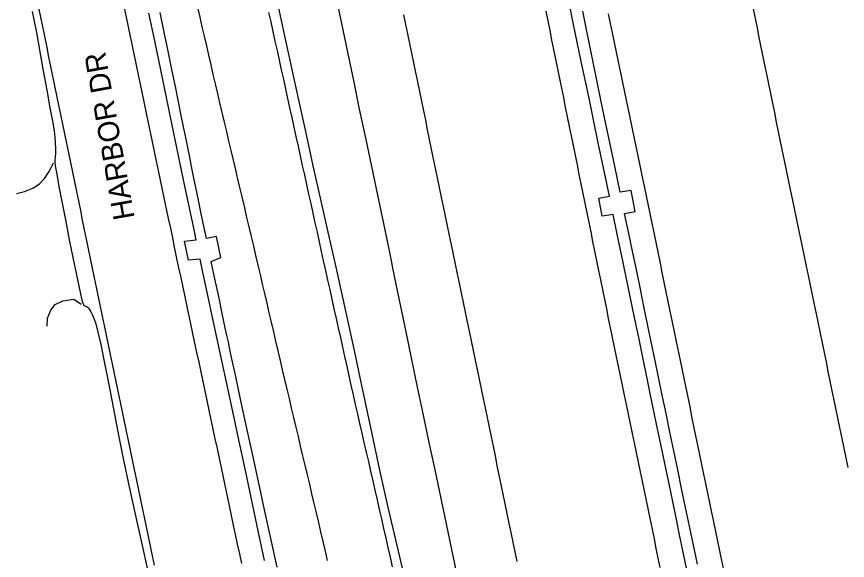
# Model space of a CAD drawing. Extents: x 1948091 to 1975253, y 787267 to 823306.
# Drawn here: x 1966655.1 to 1966867.3, y 788495.7 to 788634.5 of the extents above; entities that cross this region are included whole.
import ezdxf

# ---------------------------------------------------------------- set-up
doc = ezdxf.new("R2010")
doc.units = 0
for name, color, linetype in [('RD_EX_Pavement_Markings', 7, 'Continuous'), ('RD_EX_Road', 7, 'Continuous'), ('RD_TX_RoadID', 7, 'Continuous')]:
    doc.layers.add(name, color=color, linetype=linetype)

msp = doc.modelspace()

# ---------------------------------------------------------------- linework, layer by layer
at = {"layer": 'RD_EX_Pavement_Markings'}
for points in [[(1966690.28, 788494.44), (1966689.77, 788496.88), (1966689.26, 788499.33), (1966688.75, 788501.78), (1966688.24, 788504.22), (1966687.72, 788506.67), (1966687.21, 788509.12), (1966686.7, 788511.56), (1966686.19, 788514.01), (1966685.68, 788516.46), (1966685.17, 788518.91), (1966684.65, 788521.35), (1966684.14, 788523.8), (1966683.63, 788526.25), (1966683.12, 788528.69), (1966682.61, 788531.14), (1966682.1, 788533.59), (1966681.58, 788536.03), (1966681.07, 788538.48), (1966680.56, 788540.93), (1966680.05, 788543.38), (1966679.54, 788545.82), (1966679.03, 788548.27), (1966678.51, 788550.72), (1966678, 788553.16), (1966677.49, 788555.61), (1966676.99, 788558.06), (1966676.48, 788560.51), (1966675.98, 788562.96), (1966675.48, 788565.41), (1966674.97, 788567.85), (1966674.47, 788570.3), (1966673.97, 788572.75), (1966673.46, 788575.2), (1966672.96, 788577.65), (1966672.46, 788580.1), (1966671.95, 788582.55), (1966671.45, 788585), (1966670.95, 788587.44), (1966670.44, 788589.89), (1966669.94, 788592.34), (1966669.44, 788594.79), (1966668.93, 788597.24), (1966668.43, 788599.69), (1966667.93, 788602.14), (1966667.42, 788604.59), (1966666.91, 788607.03), (1966666.4, 788609.48), (1966665.89, 788611.93), (1966665.39, 788614.38), (1966664.88, 788616.82), (1966664.37, 788619.27), (1966663.86, 788621.72), (1966663.35, 788624.17), (1966662.84, 788626.61), (1966662.33, 788629.06), (1966661.82, 788631.51), (1966661.31, 788633.96), (1966660.8, 788636.4)], [(1966712.58, 788494.91), (1966712.06, 788497.35), (1966711.54, 788499.8), (1966711.02, 788502.25), (1966710.5, 788504.69), (1966709.98, 788507.14), (1966709.46, 788509.58), (1966708.94, 788512.03), (1966708.43, 788514.47), (1966707.91, 788516.92), (1966707.39, 788519.36), (1966706.87, 788521.81), (1966706.35, 788524.26), (1966705.83, 788526.7), (1966705.31, 788529.15), (1966704.79, 788531.59), (1966704.27, 788534.04), (1966703.75, 788536.48), (1966703.23, 788538.93), (1966702.71, 788541.37), (1966702.19, 788543.82), (1966701.67, 788546.26), (1966701.15, 788548.71), (1966700.63, 788551.15), (1966700.11, 788553.6), (1966699.59, 788556.04), (1966699.07, 788558.49), (1966698.55, 788560.93), (1966698.03, 788563.38), (1966697.51, 788565.82), (1966696.99, 788568.27), (1966696.47, 788570.72), (1966695.96, 788573.16), (1966695.45, 788575.61), (1966694.94, 788578.06), (1966694.43, 788580.5), (1966693.91, 788582.95), (1966693.4, 788585.4), (1966692.89, 788587.84), (1966692.38, 788590.29), (1966691.87, 788592.74), (1966691.36, 788595.19), (1966690.84, 788597.63), (1966690.33, 788600.08), (1966689.82, 788602.53), (1966689.31, 788604.97), (1966688.8, 788607.42), (1966688.29, 788609.87), (1966687.77, 788612.31), (1966687.26, 788614.76), (1966686.75, 788617.21), (1966686.24, 788619.66), (1966685.73, 788622.1), (1966685.22, 788624.55), (1966684.71, 788627), (1966684.19, 788629.44), (1966683.68, 788631.89), (1966683.17, 788634.34), (1966682.66, 788636.78)], [(1966701.3, 788636.8), (1966701.87, 788634.37), (1966702.43, 788631.93), (1966702.99, 788629.49), (1966703.56, 788627.06), (1966704.12, 788624.62), (1966704.68, 788622.19), (1966705.24, 788619.75), (1966705.81, 788617.31), (1966706.37, 788614.88), (1966706.94, 788612.45), (1966707.52, 788610.01), (1966708.09, 788607.58), (1966708.67, 788605.15), (1966709.24, 788602.71), (1966709.82, 788600.28), (1966710.39, 788597.85), (1966710.96, 788595.41), (1966711.54, 788592.98), (1966712.11, 788590.55), (1966712.69, 788588.12), (1966713.26, 788585.68), (1966713.84, 788583.25), (1966714.41, 788580.82), (1966714.99, 788578.38), (1966715.56, 788575.95), (1966716.12, 788573.51), (1966716.69, 788571.08), (1966717.26, 788568.65), (1966717.83, 788566.21), (1966718.4, 788563.78), (1966718.97, 788561.34), (1966719.54, 788558.91), (1966720.11, 788556.47), (1966720.68, 788554.04), (1966721.24, 788551.61), (1966721.81, 788549.17), (1966722.38, 788546.74), (1966722.95, 788544.3), (1966723.52, 788541.87), (1966724.09, 788539.43), (1966724.67, 788537), (1966725.25, 788534.57), (1966725.82, 788532.14), (1966726.4, 788529.7), (1966726.98, 788527.27), (1966727.55, 788524.84), (1966728.13, 788522.41), (1966728.71, 788519.97), (1966729.28, 788517.54), (1966729.86, 788515.11), (1966730.44, 788512.68), (1966731.01, 788510.24), (1966731.59, 788507.81), (1966732.17, 788505.38), (1966732.73, 788502.94), (1966733.3, 788500.51), (1966733.87, 788498.07), (1966734.43, 788495.64)], [(1966867.51, 788519.41), (1966867, 788521.86), (1966866.49, 788524.31), (1966865.99, 788526.76), (1966865.48, 788529.21), (1966864.97, 788531.65), (1966864.46, 788534.1), (1966863.95, 788536.55), (1966863.44, 788539), (1966862.93, 788541.44), (1966862.42, 788543.89), (1966861.91, 788546.34), (1966861.4, 788548.79), (1966860.89, 788551.23), (1966860.39, 788553.68), (1966859.88, 788556.13), (1966859.37, 788558.58), (1966858.86, 788561.02), (1966858.35, 788563.47), (1966857.84, 788565.92), (1966857.33, 788568.37), (1966856.82, 788570.81), (1966856.31, 788573.26), (1966855.8, 788575.71), (1966855.3, 788578.16), (1966854.79, 788580.6), (1966854.28, 788583.05), (1966853.77, 788585.5), (1966853.26, 788587.95), (1966852.75, 788590.39), (1966852.24, 788592.84), (1966851.73, 788595.29), (1966851.23, 788597.74), (1966850.73, 788600.19), (1966850.22, 788602.64), (1966849.72, 788605.09), (1966849.22, 788607.53), (1966848.72, 788609.98), (1966848.22, 788612.43), (1966847.71, 788614.88), (1966847.21, 788617.33), (1966846.71, 788619.78), (1966846.21, 788622.23), (1966845.7, 788624.68), (1966845.2, 788627.13), (1966844.7, 788629.58), (1966844.2, 788632.02), (1966843.7, 788634.47), (1966843.19, 788636.92)], [(1966719.46, 788635.59), (1966719.99, 788633.15), (1966720.53, 788630.7), (1966721.07, 788628.26), (1966721.6, 788625.82), (1966722.14, 788623.38), (1966722.67, 788620.94), (1966723.21, 788618.5), (1966723.75, 788616.05), (1966724.28, 788613.61), (1966724.82, 788611.17), (1966725.36, 788608.73), (1966725.9, 788606.29), (1966726.43, 788603.85), (1966726.97, 788601.4), (1966727.51, 788598.96), (1966728.05, 788596.52), (1966728.58, 788594.08), (1966729.12, 788591.64), (1966729.66, 788589.2), (1966730.2, 788586.76), (1966730.73, 788584.31), (1966731.27, 788581.87), (1966731.81, 788579.43), (1966732.34, 788576.99), (1966732.88, 788574.55), (1966733.42, 788572.11), (1966733.96, 788569.67), (1966734.5, 788567.23), (1966735.05, 788564.79), (1966735.59, 788562.35), (1966736.13, 788559.91), (1966736.68, 788557.47), (1966737.22, 788555.03), (1966737.77, 788552.59), (1966738.31, 788550.14), (1966738.85, 788547.7), (1966739.4, 788545.26), (1966739.94, 788542.82), (1966740.49, 788540.38), (1966741.03, 788537.94), (1966741.58, 788535.51), (1966742.14, 788533.07), (1966742.69, 788530.63), (1966743.25, 788528.19), (1966743.81, 788525.76), (1966744.36, 788523.32), (1966744.92, 788520.88), (1966745.47, 788518.44), (1966746.03, 788516.01), (1966746.58, 788513.57), (1966747.14, 788511.13), (1966747.7, 788508.7), (1966748.25, 788506.26), (1966748.81, 788503.82), (1966749.36, 788501.38), (1966749.92, 788498.95), (1966750.47, 788496.51), (1966751.03, 788494.07)], [(1966753.93, 788634.96), (1966754.44, 788632.51), (1966754.94, 788630.06), (1966755.45, 788627.61), (1966755.95, 788625.16), (1966756.46, 788622.72), (1966756.96, 788620.27), (1966757.46, 788617.82), (1966757.97, 788615.37), (1966758.47, 788612.92), (1966758.98, 788610.47), (1966759.48, 788608.02), (1966759.98, 788605.58), (1966760.49, 788603.13), (1966760.99, 788600.68), (1966761.5, 788598.23), (1966762, 788595.78), (1966762.51, 788593.33), (1966763.01, 788590.88), (1966763.52, 788588.44), (1966764.03, 788585.99), (1966764.54, 788583.54), (1966765.05, 788581.09), (1966765.56, 788578.65), (1966766.07, 788576.2), (1966766.57, 788573.75), (1966767.08, 788571.3), (1966767.59, 788568.86), (1966768.1, 788566.41), (1966768.61, 788563.96), (1966769.12, 788561.52), (1966769.63, 788559.07), (1966770.14, 788556.62), (1966770.65, 788554.17), (1966771.16, 788551.73), (1966771.67, 788549.28), (1966772.18, 788546.83), (1966772.69, 788544.38), (1966773.2, 788541.94), (1966773.71, 788539.49), (1966774.22, 788537.04), (1966774.73, 788534.59), (1966775.24, 788532.15), (1966775.75, 788529.7), (1966776.26, 788527.25), (1966776.77, 788524.8), (1966777.28, 788522.36), (1966777.78, 788519.91), (1966778.29, 788517.46), (1966778.79, 788515.01), (1966779.3, 788512.56), (1966779.8, 788510.11), (1966780.31, 788507.67), (1966780.82, 788505.22), (1966781.32, 788502.77), (1966781.83, 788500.32), (1966782.33, 788497.87), (1966782.84, 788495.42)], [(1966790.24, 788635.86), (1966790.74, 788633.41), (1966791.24, 788630.96), (1966791.74, 788628.51), (1966792.24, 788626.06), (1966792.74, 788623.61), (1966793.24, 788621.16), (1966793.74, 788618.71), (1966794.24, 788616.26), (1966794.74, 788613.82), (1966795.24, 788611.37), (1966795.74, 788608.92), (1966796.23, 788606.47), (1966796.73, 788604.02), (1966797.23, 788601.57), (1966797.73, 788599.12), (1966798.23, 788596.67), (1966798.73, 788594.22), (1966799.23, 788591.77), (1966799.73, 788589.32), (1966800.23, 788586.87), (1966800.73, 788584.42), (1966801.23, 788581.97), (1966801.72, 788579.52), (1966802.22, 788577.07), (1966802.72, 788574.62), (1966803.22, 788572.17), (1966803.72, 788569.72), (1966804.22, 788567.27), (1966804.72, 788564.82), (1966805.22, 788562.37), (1966805.72, 788559.92), (1966806.22, 788557.47), (1966806.71, 788555.02), (1966807.21, 788552.57), (1966807.71, 788550.12), (1966808.21, 788547.68), (1966808.71, 788545.23), (1966809.22, 788542.78), (1966809.73, 788540.33), (1966810.24, 788537.88), (1966810.75, 788535.44), (1966811.26, 788532.99), (1966811.77, 788530.54), (1966812.28, 788528.09), (1966812.79, 788525.65), (1966813.3, 788523.2), (1966813.81, 788520.75), (1966814.32, 788518.3), (1966814.83, 788515.86), (1966815.34, 788513.41), (1966815.85, 788510.96), (1966816.36, 788508.51), (1966816.87, 788506.07), (1966817.38, 788503.62), (1966817.89, 788501.17), (1966818.4, 788498.73), (1966818.91, 788496.28), (1966819.42, 788493.83)], [(1966806.2, 788635.22), (1966806.71, 788632.77), (1966807.22, 788630.33), (1966807.73, 788627.88), (1966808.24, 788625.43), (1966808.75, 788622.98), (1966809.26, 788620.54), (1966809.77, 788618.09), (1966810.28, 788615.64), (1966810.79, 788613.19), (1966811.3, 788610.75), (1966811.81, 788608.3), (1966812.32, 788605.85), (1966812.83, 788603.4), (1966813.34, 788600.96), (1966813.84, 788598.51), (1966814.35, 788596.06), (1966814.86, 788593.62), (1966815.37, 788591.17), (1966815.88, 788588.72), (1966816.39, 788586.27), (1966816.9, 788583.83), (1966817.41, 788581.38), (1966817.91, 788578.93), (1966818.42, 788576.48), (1966818.92, 788574.03), (1966819.43, 788571.58), (1966819.93, 788569.13), (1966820.44, 788566.69), (1966820.94, 788564.24), (1966821.45, 788561.79), (1966821.95, 788559.34), (1966822.46, 788556.89), (1966822.96, 788554.44), (1966823.47, 788552), (1966823.97, 788549.55), (1966824.48, 788547.1), (1966824.98, 788544.65), (1966825.49, 788542.2), (1966825.99, 788539.75), (1966826.5, 788537.31), (1966827, 788534.86), (1966827.51, 788532.41), (1966828.02, 788529.96), (1966828.52, 788527.51), (1966829.03, 788525.06), (1966829.53, 788522.62), (1966830.04, 788520.17), (1966830.54, 788517.72), (1966831.05, 788515.27), (1966831.56, 788512.82), (1966832.07, 788510.38), (1966832.57, 788507.93), (1966833.08, 788505.48), (1966833.59, 788503.03), (1966834.1, 788500.58), (1966834.6, 788498.14), (1966835.11, 788495.69), (1966835.62, 788493.24)]]:
    msp.add_lwpolyline(points, dxfattribs=at)
at = {"layer": 'RD_EX_Road'}
for points in [[(1966754.04, 788491.93), (1966751.93, 788500.9), (1966749.92, 788509.59), (1966747.89, 788518.7), (1966745.88, 788528.01), (1966744.27, 788535.6), (1966743.03, 788541.51), (1966741.63, 788548.03), (1966740.01, 788555.47), (1966738.3, 788563.25), (1966736.53, 788571.26), (1966734.69, 788579.46), (1966732.79, 788587.84), (1966730.87, 788596.44), (1966728.95, 788605.18), (1966727.1, 788613.63), (1966725.31, 788621.75), (1966723.53, 788629.93), (1966721.72, 788638.23)], [(1966736.55, 788640.07), (1966738.07, 788632.72), (1966739.58, 788625.45), (1966741.09, 788618.19), (1966742.62, 788610.91), (1966744.16, 788603.58), (1966745.72, 788596.21), (1966747.26, 788588.9), (1966748.76, 788581.72), (1966750.22, 788574.69), (1966751.64, 788567.8), (1966753.05, 788560.94), (1966754.49, 788554), (1966755.95, 788546.99), (1966757.43, 788539.89), (1966758.92, 788532.79), (1966760.4, 788525.75), (1966761.87, 788518.77), (1966763.32, 788511.86), (1966764.77, 788504.97), (1966766.22, 788498.07), (1966767.68, 788491.16)], [(1966826.29, 788493.23), (1966825.34, 788497.78), (1966824.42, 788502.2), (1966823.53, 788506.5), (1966822.67, 788510.68), (1966821.82, 788514.77), (1966820.98, 788518.83), (1966820.14, 788522.85), (1966819.31, 788526.84), (1966818.48, 788530.85), (1966817.63, 788534.95), (1966816.76, 788539.13), (1966815.88, 788543.4), (1966814.96, 788547.86), (1966813.98, 788552.61), (1966812.93, 788557.66), (1966811.82, 788563.01), (1966810.69, 788568.44), (1966809.59, 788573.75), (1966808.51, 788578.94), (1966807.46, 788584), (1966804.68, 788583.58), (1966803.78, 788588.19), (1966806.5, 788588.66), (1966804.99, 788595.89), (1966803.66, 788602.25), (1966802.52, 788607.74), (1966801.55, 788612.36), (1966800.61, 788616.83), (1966799.56, 788621.88), (1966798.39, 788627.52), (1966797.11, 788633.74), (1966795.79, 788640.12)], [(1966659.07, 788635.79), (1966660.12, 788630.43), (1966661.04, 788625.47), (1966661.9, 788620.65), (1966662.79, 788615.71), (1966663.59, 788611.24), (1966664.21, 788607.83), (1966664.64, 788605.34), (1966664.85, 788603.63), (1966664.95, 788602.26), (1966665.01, 788600.81), (1966665.01, 788599.51), (1966664.92, 788598.58), (1966664.82, 788597.91), (1966664.8, 788597.63), (1966664.8, 788597.39), (1966664.94, 788596.4), (1966665.31, 788594.31), (1966665.9, 788591.13), (1966666.71, 788586.89), (1966667.62, 788582.16), (1966668.54, 788577.53), (1966669.45, 788573), (1966670.35, 788568.59), (1966671.12, 788564.9), (1966671.63, 788562.53), (1966671.83, 788561.77), (1966672.04, 788561.21), (1966672.27, 788560.85), (1966672.51, 788560.69), (1966672.74, 788560.61), (1966672.97, 788560.49), (1966673.18, 788560.32), (1966673.38, 788560.11), (1966673.58, 788559.85), (1966674.01, 788559.16), (1966674.46, 788558.26), (1966674.89, 788557.25), (1966675.31, 788556.04), (1966675.86, 788553.92), (1966676.55, 788550.75), (1966677.46, 788546.42), (1966678.57, 788540.97), (1966679.76, 788534.8), (1966681.01, 788528.06), (1966682.37, 788521.27), (1966683.85, 788514.47), (1966685.38, 788507.47), (1966686.96, 788500.27), (1966688.56, 788492.94)], [(1966718.38, 788495.62), (1966716.75, 788503.25), (1966715.74, 788508.04), (1966714.64, 788513.31), (1966713.43, 788519.08), (1966712.12, 788525.22), (1966710.91, 788530.91), (1966709.79, 788536.09), (1966708.67, 788541.19), (1966707.55, 788546.26), (1966705.54, 788555.7), (1966703.56, 788564.93), (1966702.49, 788569.99), (1966701.95, 788572.6), (1966699.01, 788572.33), (1966697.98, 788577.2), (1966700.94, 788577.49), (1966700.23, 788580.92), (1966699.09, 788586.42), (1966697.74, 788592.86), (1966696.19, 788600.2), (1966694.74, 788607.23), (1966693.38, 788613.88), (1966691.92, 788620.91), (1966690.35, 788628.33), (1966688.85, 788635.37)], [(1966721.6, 788493.93), (1966720.01, 788501.25), (1966718.41, 788508.59), (1966716.84, 788515.8), (1966715.31, 788522.87), (1966713.8, 788529.81), (1966712.37, 788536.44), (1966711.05, 788542.59), (1966709.83, 788548.26), (1966709.17, 788551.41), (1966708.73, 788553.45), (1966707.7, 788558.32), (1966706.7, 788563.03), (1966705.73, 788567.59), (1966704.79, 788571.99), (1966707.27, 788572.97), (1966706.11, 788578.37), (1966703.59, 788577.84), (1966702.26, 788584.14), (1966701.51, 788587.68), (1966700.85, 788590.87), (1966700.26, 788593.72), (1966699.76, 788596.23), (1966699.29, 788598.62), (1966698.79, 788601.1), (1966698.27, 788603.67), (1966697.73, 788606.34), (1966697.12, 788609.29), (1966696.42, 788612.72), (1966695.63, 788616.63), (1966694.73, 788621.01), (1966693.77, 788625.71), (1966692.76, 788630.54), (1966691.71, 788635.51)], [(1966828.96, 788494.75), (1966827.96, 788499.57), (1966826.96, 788504.38), (1966825.96, 788509.19), (1966824.95, 788514.01), (1966823.95, 788518.81), (1966822.96, 788523.62), (1966821.96, 788528.42), (1966820.97, 788533.19), (1966820, 788537.87), (1966819.04, 788542.48), (1966818.1, 788547.01), (1966817.16, 788551.49), (1966816.23, 788555.97), (1966815.31, 788560.45), (1966814.4, 788564.92), (1966813.47, 788569.48), (1966812.49, 788574.21), (1966811.46, 788579.13), (1966810.39, 788584.22), (1966813.06, 788584.77), (1966812.07, 788590.14), (1966809.28, 788589.64), (1966807.87, 788596.3), (1966806.59, 788602.38), (1966805.45, 788607.88), (1966804.43, 788612.79), (1966803.49, 788617.4), (1966802.54, 788622.02), (1966801.59, 788626.63), (1966800.64, 788631.24), (1966799.69, 788635.85)], [(1966655.08, 788589.35), (1966657.05, 788589.85), (1966659.21, 788590.72), (1966660.93, 788591.8), (1966662.2, 788593.16), (1966663.37, 788594.99), (1966664.54, 788597.15)], [(1966662.9, 788555.45), (1966662.93, 788557.52), (1966663.86, 788559.52), (1966664.92, 788561), (1966666.92, 788561.9), (1966669.66, 788562.34), (1966671.57, 788561.12)]]:
    msp.add_lwpolyline(points, dxfattribs=at)

# ---------------------------------------------------------------- texts
at = {"layer": 'RD_TX_RoadID'}
msp.add_text('HARBOR DR', height=5.4, rotation=100.0968, dxfattribs=at).set_placement((1966685.25, 788583.12))

doc.saveas('drawing.dxf')
